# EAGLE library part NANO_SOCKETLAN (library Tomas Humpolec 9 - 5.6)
Miniaturní Ethernet modul Nano SocketLAN Hardware - Velikost: 35.0 x 24.88 x 17.4 mm - Konektory: Molex 52991-0308 // 2x10 pin header (RM=2mm) - Procesor: iChip? CO2144 Interface - 3V UART (Rx, Tx, RTS, CTS) - USB - SPI - Ethernet (RJ-45 se dv?ma LED) Host Data Rate - UART: a? 3Mbps - SPI: a? 12Mbps Ostatní parametry - Teplotní rozsah -40° a? 85°C - Napájecí nap?tí +3,3V (+/-10%) - ROHS Ano - Spot?eba: 130 mA (150 mA max.) - Security: SSL3/TLS1, HTTPS, FTPS, RSA, AES-128/256, 3DES, RC-4, SHA-1, MD-5 - Protokoly: ARP, ICMP, IP, UDP, TCP, DHCP, DNS, NTP, SMTP, POP3, MIME, HTTP, - FTP and Telnet Clients - Embedded Web Server 2 web servery - u?ivatelský a konfigura?ní u?ivatelský web server m??e obsahovat: HTML kód, grafiku, text. soubory, Java Applety,WAP stránky, atd. ... maximální velikost u?ivatelského web serveru je 256kB* - Hardwarov? akcelerované protokoly: AES, 3DES and SHA API Connect One?s AT+i protocol - SerialNET mode for transparent serial data-to-Internet bridging Dal?í vlastnosti - LAN-WiFi transparent bridging - SerialNET mode for Serial-to-IP bridging (port server mode) - PPP operation mode for Modem-LAN conversion - AT+i protocol for Internet Controller mode - Local firmware update - Remote configuration and firmware update over the Internet - Retrieval of time data from a Network Time Server - True hardware random number generator - DHCP Server/Client http://www.spezial.cz/connectone/index.html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
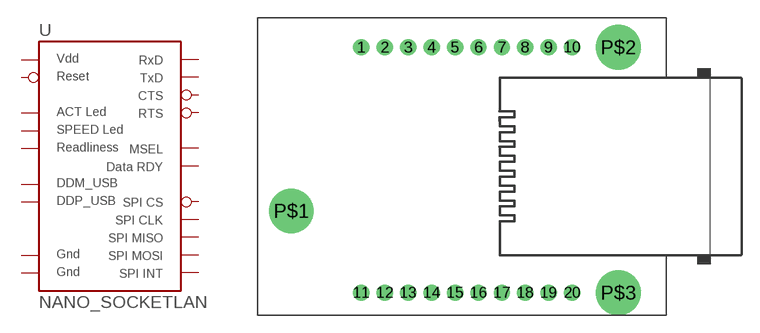
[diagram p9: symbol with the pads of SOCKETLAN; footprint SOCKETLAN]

Designator prefix -

## NANO_SOCKETLANDIP_2MM  [SOCKETLAN]
1  1  pwr
2  2  pwr
3  3  in
4  4  out
5  5  in
6  6  out
7  7  out
8  8  in
9  9  in
10  10  out
11  11  in
12  12  in
13  13  out
14  14  in
15  15  out
16  16  out
17  17
18  18
19  19  out
20  20  pwr

## Footprint SOCKETLAN (pad centres in mm)
drill 0.889 round: 1 8.89,22.86; 2 10.89,22.86; 3 12.89,22.86; 4 14.89,22.86; 5 16.89,22.86; 6 18.89,22.86; 7 20.89,22.86; 8 22.89,22.86; 9 24.89,22.86; 10 26.89,22.86; 11 8.89,1.905; 12 10.89,1.905; 13 12.89,1.905; 14 14.89,1.905; 15 16.89,1.905; 16 18.89,1.905; 17 20.89,1.905; 18 22.89,1.905; 19 24.89,1.905; 20 26.89,1.905
drill 2.8 pad 3.81 round: P$1 2.905,8.89; P$2 30.845,22.86; P$3 30.845,1.905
